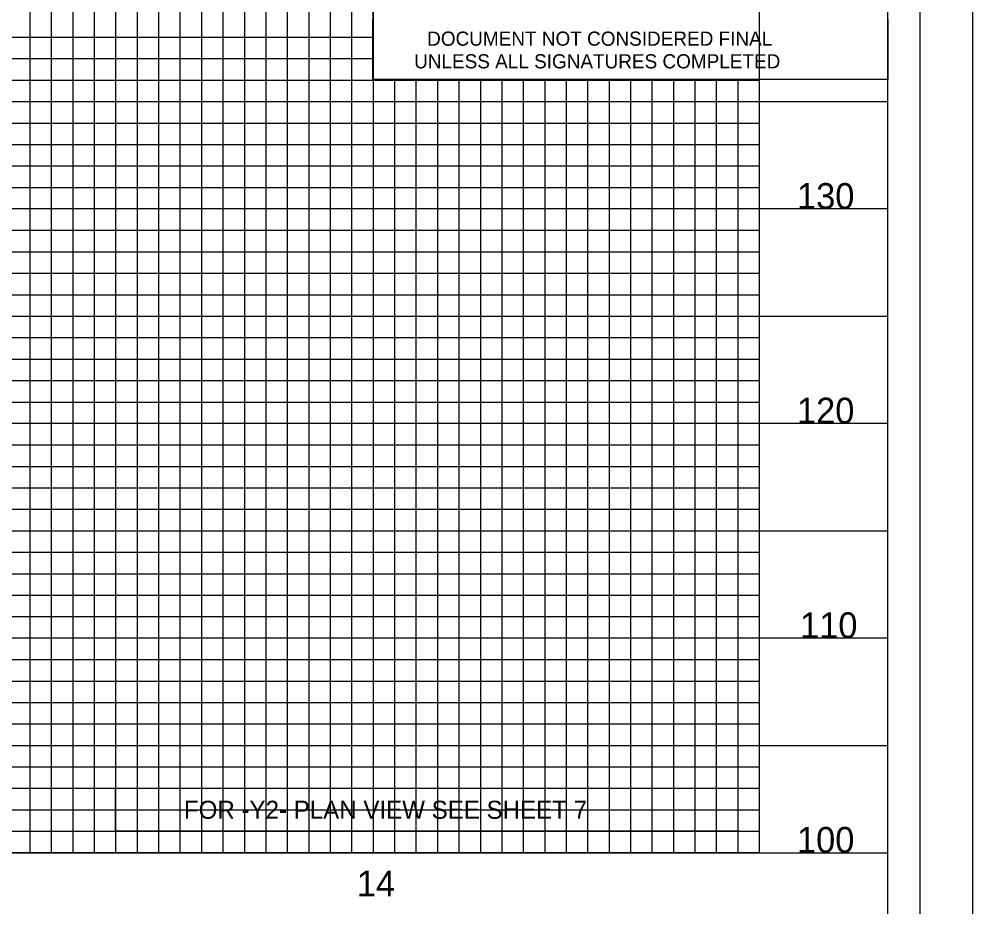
# Model space of a CAD drawing. Extents: x 270 to 1290, y -4845 to -4185.
# Drawn here: x 1067.5 to 1289.8, y -4512.4 to -4305.5 of the extents above; entities that cross this region are included whole.
import ezdxf

# ---------------------------------------------------------------- set-up
doc = ezdxf.new("R2010")
doc.units = 0
for name, color, linetype in [('Exist Vertical Profile Horizontal Axis Label Major', 7, 'Continuous'), ('Exist Vertical Profile Vertical Axis Label', 7, 'Continuous'), ('Prop Grid Mask', 7, 'Continuous'), ('Prop PFL Text', 7, 'Continuous'), ('Scratch_Level_1', 7, 'Continuous'), ('Sheet Cutting Line CELL', 7, 'Continuous'), ('Sheet Layout Profile Border Port 1', 7, 'Continuous'), ('Sheet Plot Border Inside CELL', 7, 'Continuous'), ('Sheet Plot Border Outside CELL', 7, 'Continuous'), ('Sheet Profile CELL', 7, 'Continuous'), ('Sheet Profile Grid Major CELL', 7, 'Continuous'), ('Sheet Profile Grid Middle CELL', 7, 'Continuous'), ('Sheet Profile Grid Minor CELL', 7, 'Continuous'), ('Sheet Sticker Exception Certification CELL', 7, 'Continuous')]:
    doc.layers.add(name, color=color, linetype=linetype)

msp = doc.modelspace()

# ---------------------------------------------------------------- linework, layer by layer
at = {"layer": 'Exist Vertical Profile Vertical Axis Label'}
msp.add_lwpolyline([(1090, -4484.75), (1235, -4484.75), (1235, -4494.75), (1090, -4494.75)], close=True, dxfattribs=at)
at = {"layer": 'Prop Grid Mask'}
msp.add_lwpolyline([(1090, -4484.75), (1235, -4484.75), (1235, -4494.75), (1090, -4494.75)], close=True, dxfattribs=at)
at = {"layer": 'Scratch_Level_1'}
msp.add_lwpolyline([(850, -4199.75), (1240, -4199.75), (1240, -4499.75), (850, -4499.75)], close=True, dxfattribs=at)
at = {"layer": 'Sheet Cutting Line CELL'}
msp.add_line((1289.8, -4844.75), (1289.8, -4184.75), dxfattribs=at)
at = {"layer": 'Sheet Layout Profile Border Port 1'}
msp.add_lwpolyline([(400, -4199.75), (1149.97, -4199.75), (1149.97, -4319.63), (1240, -4319.75), (1240, -4499.75), (400, -4499.75)], close=True, dxfattribs=at)
at = {"layer": 'Sheet Plot Border Inside CELL'}
msp.add_lwpolyline([(277.6, -4831.28), (1277.5, -4831.28), (1277.5, -4198.22), (277.6, -4198.22)], close=True, dxfattribs=at)
at = {"layer": 'Sheet Plot Border Outside CELL'}
msp.add_lwpolyline([(269.8, -4844.75), (1289.8, -4844.75), (1289.8, -4184.75), (269.8, -4184.75)], close=True, dxfattribs=at)
at = {"layer": 'Sheet Profile CELL'}
msp.add_line((370, -4499.75), (1270, -4499.75), dxfattribs=at)
msp.add_lwpolyline([(1270, -4199.75), (370, -4199.75), (370, -4829.75), (1270, -4829.75)], close=True, dxfattribs=at)
at = {"layer": 'Sheet Profile Grid Major CELL'}
for p, q in [((1075, -4199.75), (1075, -4499.75)), ((1100, -4199.75), (1100, -4499.75)), ((1125, -4199.75), (1125, -4499.75)), ((1150, -4199.75), (1150, -4499.75)), ((1175, -4319.63), (1175, -4499.75)), ((1200, -4319.63), (1200, -4499.75)), ((1225, -4319.63), (1225, -4499.75)), ((1240, -4319.63), (1240, -4499.75)), ((370, -4324.75), (1270, -4324.75)), ((1270, -4349.75), (370, -4349.75)), ((370, -4374.75), (1270, -4374.75)), ((1270, -4399.75), (370, -4399.75)), ((370, -4424.75), (1270, -4424.75)), ((1270, -4449.75), (370, -4449.75)), ((370, -4474.75), (1270, -4474.75))]:
    msp.add_line(p, q, dxfattribs=at)
at = {"layer": 'Sheet Profile Grid Middle CELL'}
for p, q in [((850, -4309.75), (1150, -4309.75)), ((850, -4314.75), (1150, -4314.75)), ((850, -4319.75), (1240, -4319.75)), ((850, -4329.75), (1240, -4329.75)), ((850, -4334.75), (1240, -4334.75)), ((850, -4339.75), (1240, -4339.75)), ((850, -4344.75), (1240, -4344.75)), ((850, -4354.75), (1240, -4354.75)), ((850, -4359.75), (1240, -4359.75)), ((850, -4364.75), (1240, -4364.75)), ((850, -4369.75), (1240, -4369.75)), ((850, -4379.75), (1240, -4379.75)), ((850, -4384.75), (1240, -4384.75)), ((850, -4389.75), (1240, -4389.75)), ((850, -4394.75), (1240, -4394.75)), ((850, -4404.75), (1240, -4404.75)), ((850, -4409.75), (1240, -4409.75)), ((850, -4414.75), (1240, -4414.75)), ((850, -4419.75), (1240, -4419.75)), ((850, -4429.75), (1240, -4429.75)), ((850, -4434.75), (1240, -4434.75)), ((850, -4439.75), (1240, -4439.75)), ((850, -4444.75), (1240, -4444.75)), ((850, -4454.75), (1240, -4454.75)), ((850, -4459.75), (1240, -4459.75)), ((850, -4464.75), (1240, -4464.75)), ((850, -4469.75), (1240, -4469.75)), ((850, -4479.75), (1240, -4479.75)), ((850, -4484.75), (1240, -4484.75)), ((850, -4489.75), (1240, -4489.75)), ((850, -4494.75), (1240, -4494.75))]:
    msp.add_line(p, q, dxfattribs=at)
msp.add_lwpolyline([(1165, -4334.75), (1240, -4334.75)], dxfattribs=at)
at = {"layer": 'Sheet Profile Grid Minor CELL'}
for p, q in [((1070, -4199.75), (1070, -4499.75)), ((1080, -4199.75), (1080, -4499.75)), ((1085, -4199.75), (1085, -4499.75)), ((1090, -4199.75), (1090, -4499.75)), ((1095, -4199.75), (1095, -4499.75)), ((1105, -4199.75), (1105, -4499.75)), ((1110, -4199.75), (1110, -4499.75)), ((1115, -4199.75), (1115, -4499.75)), ((1120, -4199.75), (1120, -4499.75)), ((1130, -4199.75), (1130, -4499.75)), ((1135, -4199.75), (1135, -4499.75)), ((1140, -4199.75), (1140, -4499.75)), ((1145, -4199.75), (1145, -4499.75)), ((1155, -4319.63), (1155, -4499.75)), ((1160, -4319.63), (1160, -4499.75)), ((1165, -4319.63), (1165, -4499.75)), ((1170, -4319.63), (1170, -4499.75)), ((1180, -4319.63), (1180, -4499.75)), ((1185, -4319.63), (1185, -4499.75)), ((1190, -4319.63), (1190, -4499.75)), ((1195, -4319.63), (1195, -4499.75)), ((1205, -4319.63), (1205, -4499.75)), ((1210, -4319.63), (1210, -4499.75)), ((1215, -4319.63), (1215, -4499.75)), ((1220, -4319.63), (1220, -4499.75)), ((1230, -4319.63), (1230, -4499.75)), ((1235, -4319.63), (1235, -4499.75))]:
    msp.add_line(p, q, dxfattribs=at)
at = {"layer": 'Sheet Sticker Exception Certification CELL'}
for p, q in [((1149.97, -4319.63), (1149.97, -4305.53)), ((1269.99, -4305.54), (1269.99, -4319.64)), ((1269.99, -4319.63), (1149.97, -4319.63))]:
    msp.add_line(p, q, dxfattribs=at)

# ---------------------------------------------------------------- texts
at = {"layer": 'Exist Vertical Profile Horizontal Axis Label Major'}
msp.add_text('14', height=6, dxfattribs=at).set_placement((1146.22, -4509.93))
at = {"layer": 'Exist Vertical Profile Vertical Axis Label'}
for s, p in [('130', (1248.79, -4349.75)), ('120', (1248.79, -4399.75)), ('110', (1249.51, -4449.75)), ('100', (1248.79, -4499.75))]:
    msp.add_text(s, height=6, dxfattribs=at).set_placement(p)
at = {"layer": 'Prop PFL Text'}
msp.add_text('FOR -Y2- PLAN VIEW SEE SHEET 7', height=4.2, dxfattribs=at).set_placement((1105.92, -4491.85))
at = {"layer": 'Sheet Sticker Exception Certification CELL'}
for s, p in [('DOCUMENT NOT CONSIDERED FINAL', (1162.61, -4311.74)), ('UNLESS ALL SIGNATURES COMPLETED', (1159.57, -4317.02))]:
    msp.add_text(s, height=3.3, rotation=0, dxfattribs=at).set_placement(p)

doc.saveas('drawing.dxf')
